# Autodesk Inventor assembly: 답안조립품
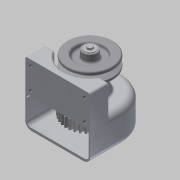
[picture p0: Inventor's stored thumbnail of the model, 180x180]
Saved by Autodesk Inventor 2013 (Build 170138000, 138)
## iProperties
Created: 2015-02
Part Number: 답안조립품
Document SubType Name: Assembly
Designer: Administrator
Author: Administrator
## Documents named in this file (14)
- C:\Users\Administrator\Desktop\450216V1005\답안조립품.iam
- C:\Users\Administrator\Desktop\450216V1005\본체.ipt
- C:\Users\Administrator\Desktop\450216V1005\베어링 6001.ipt
- C:\Users\Administrator\Desktop\450216V1005\축.ipt
- C:\Users\Administrator\Desktop\450216V1005\키4x4.ipt
- C:\Users\Administrator\Desktop\450216V1005\키5x5.ipt
- C:\Users\Administrator\Desktop\450216V1005\스퍼기어.ipt
- C:\Users\Administrator\Desktop\450216V1005\오일실.ipt
- C:\Users\Administrator\Desktop\450216V1005\축커버.ipt
- C:\Users\Administrator\Desktop\450216V1005\M3x0.5.ipt
- C:\Users\Administrator\Desktop\450216V1005\V-벨트풀리.ipt
- C:\Users\Administrator\Desktop\450216V1005\M5x0.8.ipt
- M5x0.8.ipt
- C:\Users\Administrator\Desktop\450216V1005\와샤.ipt
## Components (6 placed, 3 different names)
1. V-벨트풀리:1 — 플러쉬:1
2. M5x0.8:1
3. M3x0.5:2
4. M3x0.5:3
5. M3x0.5:4
6. M3x0.5:5
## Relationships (1: Flush 1)
- 플러쉬:1 [Flush]: V-벨트풀리:1
